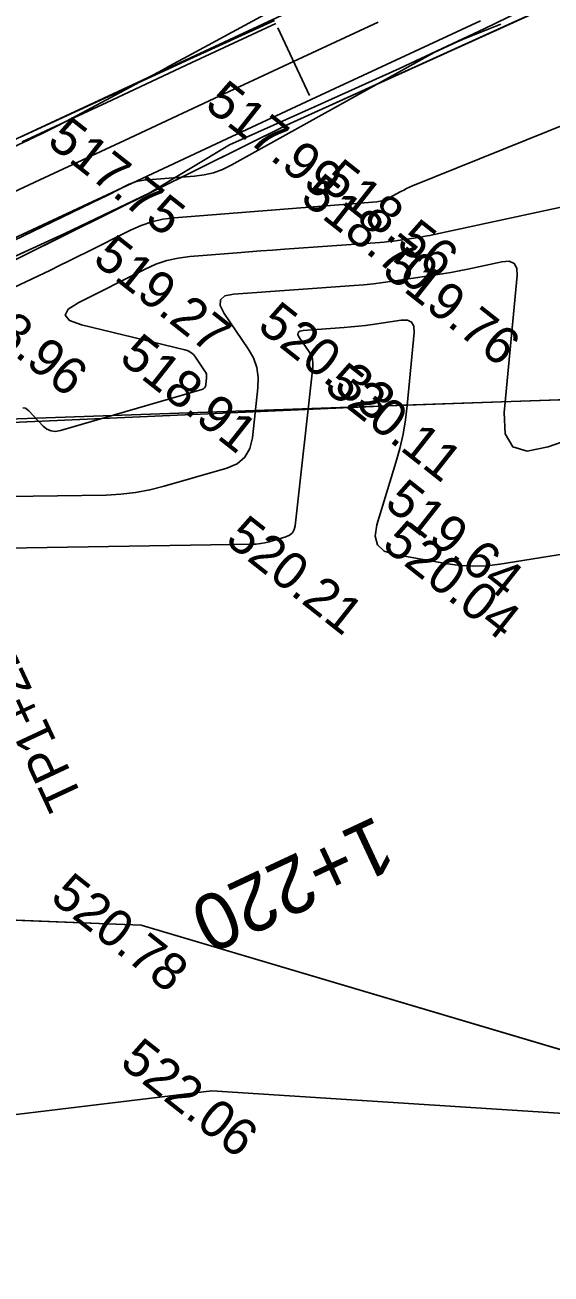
# Model space of a CAD drawing. Extents: x -636600 to -628587, y -1090963 to -1085869.
# Drawn here: x -629516.8 to -629488.6, y -1089692.4 to -1089625.5 of the extents above; entities that cross this region are included whole.
import ezdxf

# ---------------------------------------------------------------- set-up
doc = ezdxf.new("R2010")
doc.units = 0
for name, color, linetype in [('01_PARCELY_NÁVRH_PC', 7, 'Continuous'), ('21', 7, 'Continuous'), ('42', 7, 'Continuous'), ('Ex_Major Contours', 7, 'Continuous'), ('Ex_Minor Contours', 7, 'Continuous'), ('HEKTOMETRY100', 7, 'Continuous'), ('HEKTOMETRY20', 7, 'Continuous'), ('HL_BODY', 7, 'Continuous'), ('koty_vše', 7, 'Continuous'), ('PARCELY_NÁVRH_SILNICE_ŽELEZNICE', 7, 'Continuous'), ('situace_osa', 7, 'Continuous'), ('situace_těleso', 7, 'Continuous'), ('situace_vozovka', 7, 'Continuous')]:
    doc.layers.add(name, color=color, linetype=linetype)

msp = doc.modelspace()

# ---------------------------------------------------------------- linework, layer by layer
at = {"layer": '01_PARCELY_NÁVRH_PC'}
for points in [[(-629254.654, -1089739.869), (-629360.834, -1089658.331), (-629368.291, -1089654.325), (-629380.483, -1089650.342), (-629407.529, -1089646.03), (-629420.129, -1089642.952), (-629431.224, -1089638.631), (-629441.359, -1089632.253), (-629462.999, -1089614.168), (-629469.387, -1089611.971), (-629476.142, -1089612.42), (-629540.496, -1089642.406), (-629554.39, -1089646.509), (-629581.677, -1089651.277), (-629593.36, -1089654.473), (-629629.454, -1089670.47), (-629647.363, -1089680.417), (-629666.288, -1089692.668)], [(-629669.229, -1089703.189), (-629636.498, -1089682.368), (-629594.828, -1089663.555), (-629566.208, -1089655.26), (-629543.029, -1089650.823), (-629502.778, -1089630.854), (-629477.842, -1089619.529), (-629472.37, -1089618.387), (-629466.831, -1089619.344), (-629458.171, -1089625.363), (-629433.235, -1089646.243), (-629378.586, -1089656.962), (-629364.857, -1089662.954), (-629248.799, -1089751.038)]]:
    msp.add_lwpolyline(points, dxfattribs=at)
at = {"layer": '21'}
for p, q in [((-629444.439, -1089644.045), (-629496.514, -1089645.872)), ((-629496.514, -1089645.872), (-629523.373, -1089647.061)), ((-629530.665, -1089672.948), (-629510.564, -1089673.739)), ((-629510.564, -1089673.739), (-629468.307, -1089686.291))]:
    msp.add_line(p, q, dxfattribs=at)
at = {"layer": '42'}
for p, q in [((-629502.778, -1089630.854), (-629476.435, -1089618.89)), ((-629536.329, -1089647.5), (-629502.778, -1089630.854)), ((-629526.066, -1089684.958), (-629506.789, -1089682.628)), ((-629506.789, -1089682.628), (-629479.805, -1089684.365))]:
    msp.add_line(p, q, dxfattribs=at)
at = {"layer": 'Ex_Major Contours'}
for points in [[(-629496.146, -1089620.677), (-629508.065, -1089627.153), (-629508.839, -1089627.573), (-629509.613, -1089627.991), (-629510.389, -1089628.408), (-629511.165, -1089628.824), (-629514.272, -1089630.483), (-629515.052, -1089630.89), (-629515.839, -1089631.283), (-629516.634, -1089631.661), (-629517.436, -1089632.024)], [(-629469.642, -1089650.928), (-629491.346, -1089654.389), (-629492.047, -1089654.471), (-629492.748, -1089654.495), (-629493.449, -1089654.461), (-629494.149, -1089654.367), (-629496.949, -1089653.878), (-629497.536, -1089653.685), (-629497.895, -1089653.354), (-629498.028, -1089652.883), (-629497.934, -1089652.273), (-629496.914, -1089648.933), (-629496.704, -1089648.18), (-629496.534, -1089647.42), (-629496.402, -1089646.651), (-629496.309, -1089645.875), (-629495.939, -1089641.966), (-629495.955, -1089641.636), (-629496.076, -1089641.417), (-629496.301, -1089641.307), (-629496.631, -1089641.308), (-629498.161, -1089641.533), (-629498.544, -1089641.585), (-629498.927, -1089641.631), (-629499.312, -1089641.669), (-629499.697, -1089641.7), (-629501.884, -1089641.857), (-629502.066, -1089641.894), (-629502.159, -1089641.974), (-629502.164, -1089642.097), (-629502.081, -1089642.263), (-629501.572, -1089643.011), (-629501.464, -1089643.203), (-629501.394, -1089643.404), (-629501.362, -1089643.615), (-629501.368, -1089643.835), (-629502.313, -1089652.327), (-629502.364, -1089652.539), (-629502.464, -1089652.709), (-629502.615, -1089652.837), (-629502.815, -1089652.924), (-629503.717, -1089653.185), (-629503.943, -1089653.243), (-629504.172, -1089653.285), (-629504.403, -1089653.312), (-629504.636, -1089653.323), (-629523.32, -1089653.613)]]:
    msp.add_lwpolyline(points, dxfattribs=at)
at = {"layer": 'Ex_Minor Contours'}
for points in [[(-629491.285, -1089625.432), (-629493.349, -1089626.267), (-629493.862, -1089626.484), (-629494.367, -1089626.716), (-629494.865, -1089626.963), (-629495.355, -1089627.226), (-629505.753, -1089632.998), (-629506.218, -1089633.226), (-629506.7, -1089633.4), (-629507.198, -1089633.521), (-629507.711, -1089633.589), (-629510.427, -1089633.805), (-629510.631, -1089633.831), (-629510.83, -1089633.876), (-629511.023, -1089633.941), (-629511.211, -1089634.024), (-629511.952, -1089634.398), (-629512.137, -1089634.49), (-629512.323, -1089634.583), (-629512.509, -1089634.674), (-629512.696, -1089634.764), (-629519.568, -1089638.079)], [(-629487.562, -1089630.686), (-629496.018, -1089634.109), (-629496.181, -1089634.178), (-629496.341, -1089634.251), (-629496.499, -1089634.33), (-629496.655, -1089634.413), (-629497.274, -1089634.757), (-629497.431, -1089634.834), (-629497.594, -1089634.893), (-629497.762, -1089634.934), (-629497.936, -1089634.957), (-629508.801, -1089635.82), (-629509.41, -1089635.898), (-629510.003, -1089636.033), (-629510.58, -1089636.225), (-629511.14, -1089636.475), (-629513.484, -1089637.655), (-629513.971, -1089637.899), (-629514.459, -1089638.141), (-629514.948, -1089638.38), (-629515.438, -1089638.618), (-629517.4, -1089639.564)], [(-629485.415, -1089634.674), (-629494.865, -1089636.715), (-629495.105, -1089636.765), (-629495.347, -1089636.811), (-629495.589, -1089636.852), (-629495.832, -1089636.89), (-629496.805, -1089637.033), (-629497.048, -1089637.066), (-629497.292, -1089637.095), (-629497.537, -1089637.119), (-629497.782, -1089637.139), (-629502.89, -1089637.504), (-629503.524, -1089637.55), (-629504.158, -1089637.598), (-629504.792, -1089637.646), (-629505.426, -1089637.696), (-629507.962, -1089637.897), (-629508.587, -1089637.977), (-629509.196, -1089638.116), (-629509.789, -1089638.313), (-629510.365, -1089638.57), (-629513.906, -1089640.353), (-629514.482, -1089640.722), (-629514.651, -1089641.045), (-629514.414, -1089641.321), (-629513.769, -1089641.551), (-629508.222, -1089642.903), (-629508.054, -1089642.96), (-629507.904, -1089643.044), (-629507.773, -1089643.154), (-629507.661, -1089643.292), (-629507.153, -1089644.038), (-629507.107, -1089644.121), (-629507.076, -1089644.208), (-629507.063, -1089644.299), (-629507.065, -1089644.394), (-629507.108, -1089644.782), (-629507.13, -1089644.871), (-629507.172, -1089644.942), (-629507.234, -1089644.995), (-629507.318, -1089645.031), (-629514.902, -1089647.232), (-629515.16, -1089647.275), (-629515.4, -1089647.248), (-629515.62, -1089647.151), (-629515.822, -1089646.984), (-629516.593, -1089646.177), (-629516.77, -1089646.034), (-629516.916, -1089646.01)], [(-629518.994, -1089650.785), (-629512.453, -1089650.684), (-629511.662, -1089650.645), (-629510.878, -1089650.554), (-629510.102, -1089650.411), (-629509.333, -1089650.216), (-629505.978, -1089649.242), (-629505.431, -1089649.006), (-629505.02, -1089648.656), (-629504.745, -1089648.191), (-629504.606, -1089647.612), (-629504.308, -1089644.934), (-629504.293, -1089644.375), (-629504.374, -1089643.841), (-629504.552, -1089643.33), (-629504.827, -1089642.843), (-629506.118, -1089640.943), (-629506.329, -1089640.523), (-629506.316, -1089640.21), (-629506.079, -1089640.007), (-629505.619, -1089639.912), (-629499.152, -1089639.449), (-629498.631, -1089639.407), (-629498.111, -1089639.355), (-629497.592, -1089639.294), (-629497.074, -1089639.223), (-629494.894, -1089638.903), (-629494.433, -1089638.831), (-629493.973, -1089638.752), (-629493.515, -1089638.665), (-629493.058, -1089638.57), (-629491.234, -1089638.176), (-629490.84, -1089638.148), (-629490.571, -1089638.261), (-629490.428, -1089638.514), (-629490.409, -1089638.909), (-629491.103, -1089646.258), (-629491.054, -1089647.408), (-629490.645, -1089648.099), (-629489.876, -1089648.33), (-629488.747, -1089648.102), (-629476.01, -1089643.644)]]:
    msp.add_lwpolyline(points, dxfattribs=at)
at = {"layer": 'HEKTOMETRY100'}
msp.add_lwpolyline([(-629501.556, -1089629.254), (-629503.247, -1089625.628)], dxfattribs=at)
at = {"layer": 'PARCELY_NÁVRH_SILNICE_ŽELEZNICE'}
for points in [[(-629239.774, -1089757.887), (-629364.857, -1089662.954), (-629378.586, -1089656.962), (-629444.439, -1089644.045), (-629521.798, -1089646.759), (-629566.208, -1089655.26), (-629594.828, -1089663.555), (-629636.498, -1089682.368), (-629669.229, -1089703.189)], [(-629683.036, -1089730.713), (-629659.95, -1089713.109), (-629620.725, -1089691.259), (-629593.679, -1089680.601), (-629530.665, -1089672.948), (-629510.564, -1089673.739), (-629468.307, -1089686.291), (-629442.518, -1089688.526), (-629376.409, -1089715.261), (-629331.288, -1089748.416)]]:
    msp.add_lwpolyline(points, dxfattribs=at)
at = {"layer": 'situace_osa'}
msp.add_lwpolyline([(-629497.87, -1089625.327), (-629502.402, -1089627.441), (-629506.933, -1089629.554), (-629511.464, -1089631.668), (-629515.996, -1089633.781), (-629520.527, -1089635.895)], dxfattribs=at)
at = {"layer": 'situace_těleso'}
for points in [[(-629487.694, -1089623.487), (-629492.182, -1089625.695), (-629496.714, -1089627.806), (-629501.273, -1089629.861), (-629505.832, -1089631.915), (-629510.145, -1089634.497), (-629514.655, -1089636.656), (-629519.201, -1089638.738)], [(-629517.065, -1089631.488), (-629512.523, -1089629.397), (-629507.976, -1089627.317), (-629503.428, -1089625.241)]]:
    msp.add_lwpolyline(points, dxfattribs=at)
at = {"layer": 'situace_vozovka'}
for points in [[(-629492.388, -1089625.253), (-629496.919, -1089627.367), (-629501.451, -1089629.48), (-629505.982, -1089631.594), (-629510.513, -1089633.707), (-629515.045, -1089635.82), (-629519.576, -1089637.934)], [(-629492.388, -1089625.253), (-629496.919, -1089627.367), (-629501.451, -1089629.48), (-629505.982, -1089631.594), (-629510.513, -1089633.707), (-629515.045, -1089635.82), (-629519.576, -1089637.934)], [(-629503.353, -1089625.402), (-629507.884, -1089627.515), (-629512.415, -1089629.629), (-629516.947, -1089631.742)], [(-629503.353, -1089625.402), (-629507.884, -1089627.515), (-629512.415, -1089629.629), (-629516.947, -1089631.742)]]:
    msp.add_lwpolyline(points, dxfattribs=at)

# ---------------------------------------------------------------- texts
at = {"layer": 'HEKTOMETRY20'}
msp.add_text('1+220', height=3, rotation=205.00474, dxfattribs=at).set_placement((-629497.949, -1089667.846))
at = {"layer": 'HL_BODY'}
msp.add_text('TP1+229,212', height=2, rotation=115.00474, dxfattribs=at).set_placement((-629513.642, -1089666.999))
at = {"layer": 'koty_vše'}
for s, p in [('517.99', (-629507.231, -1089629.889)), ('517.75', (-629515.69, -1089631.837)), ('518.56', (-629501.052, -1089634.102)), ('518.70', (-629502.114, -1089634.881)), ('519.27', (-629513.241, -1089638.165)), ('519.76', (-629497.734, -1089638.795)), ('518.96', (-629520.917, -1089640.426)), ('520.33', (-629504.413, -1089641.755)), ('518.91', (-629511.821, -1089643.463)), ('520.11', (-629500.837, -1089645.009)), ('519.64', (-629497.595, -1089651.261)), ('520.21', (-629506.133, -1089653.212)), ('520.04', (-629497.731, -1089653.472)), ('520.78', (-629515.518, -1089672.378)), ('522.06', (-629511.786, -1089681.233))]:
    msp.add_text(s, height=2, rotation=321.72649, dxfattribs=at).set_placement(p)

doc.saveas('drawing.dxf')
